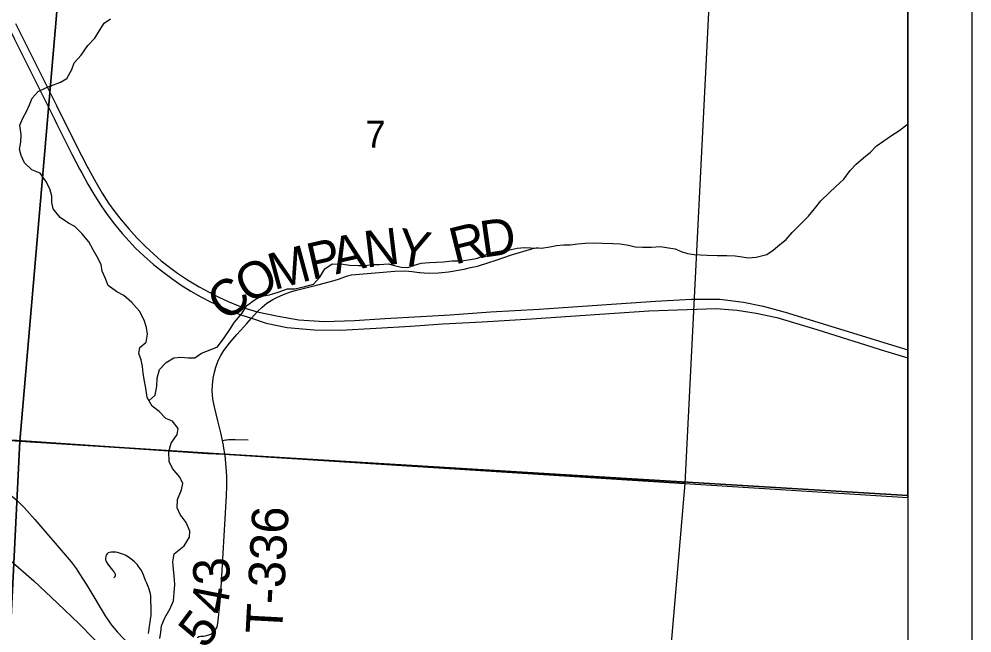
# Model space of a CAD drawing. Extents: x 0 to 34, y 0 to 22.
# Drawn here: x 7.515 to 9, y 18.417 to 19.373 of the extents above; entities that cross this region are included whole.
import ezdxf

# ---------------------------------------------------------------- set-up
doc = ezdxf.new("R2010")
doc.units = 0
for name, color, linetype in [('GM_X_Corporation', 7, 'Continuous'), ('GM_X_County_Road', 7, 'Continuous'), ('GM_X_Minor_River', 7, 'Continuous'), ('GM_X_Rail_Line', 7, 'Continuous'), ('GM_X_Section_Text', 7, 'Continuous'), ('GM_X_Township_Road', 7, 'Continuous'), ('GM_X_Township_Road_Text', 7, 'Continuous'), ('GM_X_Township_Text', 7, 'Continuous'), ('GM_X_US_Route', 7, 'Continuous'), ('SH_Data', 7, 'Continuous')]:
    doc.layers.add(name, color=color, linetype=linetype)

msp = doc.modelspace()

# ---------------------------------------------------------------- linework, layer by layer
at = {"layer": 'GM_X_Corporation'}
for points in [[(8.9, 18.631), (8.9, 20.9), (3.6477, 20.9), (3.6464, 20.8827), (3.5665, 19.797), (3.566, 19.7906), (3.507, 18.9883), (4.2931, 18.935), (4.421, 18.9263), (4.4362, 18.9253), (5.6003, 18.8464), (6.4706, 18.7873), (6.895, 18.7585), (7.0255, 18.7497), (7.0714, 18.7466), (7.0845, 18.7457), (7.389, 18.725), (7.8088, 18.6965), (7.8353, 18.6952)], [(6.5798, 19.8114), (7.5941, 19.7583), (7.5958, 19.6386), (7.5162, 18.7157), (6.5391, 18.7835)], [(7.5941, 19.7583), (8.6057, 19.704), (8.5526, 18.6497), (7.5162, 18.7157), (7.5958, 19.6386)], [(8.9, 18.6277), (8.9, 19.6882), (8.6057, 19.704), (8.5526, 18.6497)], [(7.5162, 18.7157), (7.4643, 17.6703), (6.4386, 17.7441), (6.5391, 18.7835)], [(8.5526, 18.6497), (8.4629, 17.601), (7.4643, 17.6703), (7.5162, 18.7157)]]:
    msp.add_lwpolyline(points, close=True, dxfattribs=at)
at = {"layer": 'GM_X_County_Road'}
msp.add_lwpolyline([(7.3969, 18.717), (7.4409, 18.6782), (7.4478, 18.6722), (7.465, 18.6589), (7.4691, 18.6558), (7.5, 18.633), (7.512, 18.6231), (7.5232, 18.6122), (7.5399, 18.5937), (7.5963, 18.5274), (7.604, 18.5172), (7.6069, 18.5131), (7.6224, 18.4887), (7.6495, 18.4434), (7.6583, 18.4307), (7.6681, 18.4187), (7.6873, 18.3985), (7.6998, 18.3856), (7.7132, 18.3716), (7.7381, 18.3433), (7.7438, 18.3366), (7.7541, 18.3251), (7.7622, 18.3159), (7.7844, 18.2905)], dxfattribs=at)
at = {"layer": 'GM_X_Minor_River'}
for points in [[(7.5451, 19.2602), (7.5579, 19.2667), (7.5685, 19.2706), (7.5798, 19.2745), (7.5896, 19.2803), (7.5971, 19.2944), (7.6011, 19.305), (7.6116, 19.3168), (7.6221, 19.3317), (7.633, 19.3432), (7.6404, 19.355), (7.6475, 19.3668), (7.6577, 19.3734)], [(7.7346, 18.4081), (7.736, 18.418), (7.737, 18.4278), (7.7422, 18.4404), (7.7508, 18.4549), (7.7556, 18.467), (7.757, 18.4796), (7.7577, 18.4921), (7.7568, 18.5053), (7.7556, 18.5163), (7.7547, 18.5277), (7.7569, 18.5402), (7.7726, 18.5528), (7.7809, 18.5658), (7.7812, 18.5753), (7.7757, 18.5889), (7.7662, 18.6013), (7.7615, 18.6115), (7.7618, 18.6247), (7.7681, 18.6396), (7.7703, 18.6498), (7.7657, 18.6596), (7.7542, 18.6728), (7.7488, 18.6837), (7.7487, 18.6993), (7.752, 18.7126), (7.7613, 18.7259), (7.7631, 18.7354), (7.7543, 18.7467), (7.7437, 18.7508), (7.7334, 18.762), (7.7227, 18.7703), (7.7146, 18.7835), (7.7126, 18.7979), (7.7099, 18.8118), (7.7083, 18.8217), (7.7074, 18.8319), (7.7054, 18.8421), (7.7016, 18.8519), (7.7034, 18.8614), (7.7131, 18.8699), (7.7153, 18.8824), (7.7137, 18.8926), (7.7102, 18.9043), (7.7029, 18.9179), (7.6906, 18.9314), (7.6784, 18.9427), (7.6674, 18.9483), (7.6537, 18.958), (7.6491, 18.9701), (7.6448, 18.9803), (7.6428, 18.9905), (7.6367, 19.0029), (7.6305, 19.0135), (7.624, 19.0259), (7.6129, 19.0391), (7.6022, 19.05), (7.5919, 19.0552), (7.579, 19.0642), (7.5683, 19.0777), (7.5659, 19.0875), (7.5659, 19.0974), (7.5631, 19.1084), (7.5569, 19.1208), (7.5478, 19.1332), (7.5348, 19.1384), (7.5238, 19.1493), (7.5184, 19.1606), (7.516, 19.1705), (7.5178, 19.1811), (7.5181, 19.1932), (7.5165, 19.2076), (7.5209, 19.2186), (7.5269, 19.2289), (7.5313, 19.2392), (7.5354, 19.2498), (7.5451, 19.2602)], [(8.8509, 19.1751), (8.8629, 19.1835), (8.8746, 19.1916), (8.8859, 19.1992), (8.899, 19.2088), (8.9, 19.2094)], [(7.7176, 18.7787), (7.7271, 18.787), (7.7296, 18.801), (7.7303, 18.8139), (7.7339, 18.8272), (7.7441, 18.8383), (7.7565, 18.8452), (7.7674, 18.8465), (7.7784, 18.8454), (7.789, 18.8452), (7.7996, 18.8525), (7.8131, 18.8579), (7.8241, 18.8625), (7.8349, 18.8763), (7.8435, 18.8896), (7.851, 18.9007), (7.8626, 18.9152), (7.87, 18.927), (7.8832, 18.9362), (7.893, 18.9416), (7.9055, 18.9436), (7.9187, 18.9479), (7.9334, 18.9526), (7.9447, 18.9531), (7.9606, 18.9566), (7.9738, 18.9602), (7.9836, 18.9712), (7.9914, 18.9842), (8.003, 18.9919), (8.0201, 18.9913), (8.0299, 18.9895), (8.0439, 18.9892), (8.0545, 18.9893), (8.0651, 18.9905), (8.0768, 18.9907), (8.0905, 18.9919), (8.0999, 18.989), (8.1106, 18.9864), (8.1208, 18.9861), (8.1313, 18.9896), (8.1415, 18.9928), (8.1548, 18.994), (8.1657, 18.9945), (8.1763, 18.995), (8.1899, 18.9966), (8.2043, 18.9964), (8.2187, 18.9984), (8.2293, 19.0004), (8.2421, 19.0058), (8.2538, 19.0101), (8.2662, 19.0121), (8.2772, 19.0133), (8.2912, 19.0161), (8.3025, 19.017), (8.3127, 19.0167), (8.3294, 19.0161), (8.3422, 19.0185), (8.3524, 19.0201), (8.3634, 19.0213), (8.374, 19.0214), (8.3857, 19.0227), (8.3974, 19.0239), (8.4107, 19.0244), (8.4243, 19.0238), (8.4406, 19.0235), (8.4519, 19.0229), (8.4648, 19.0211), (8.4754, 19.0185), (8.4864, 19.0175), (8.5004, 19.018), (8.5148, 19.0189), (8.5273, 19.0167), (8.5375, 19.0149), (8.547, 19.0112), (8.5569, 19.0079), (8.5671, 19.0065), (8.5769, 19.0058), (8.5872, 19.0052), (8.603, 19.0049), (8.6178, 19.0047), (8.6311, 19.0044), (8.6417, 19.0026), (8.6511, 19.0012), (8.6636, 19.0021), (8.6806, 19.0064), (8.6904, 19.0129), (8.7005, 19.0221), (8.7103, 19.0298), (8.72, 19.0405), (8.7335, 19.0542), (8.7452, 19.0661), (8.7545, 19.0772), (8.7646, 19.0898), (8.7778, 19.1031), (8.7875, 19.1116), (8.8003, 19.1238), (8.8104, 19.1372), (8.8198, 19.1471), (8.831, 19.1567), (8.8419, 19.1655), (8.8509, 19.1751)]]:
    msp.add_lwpolyline(points, dxfattribs=at)
at = {"layer": 'GM_X_Rail_Line'}
msp.add_lwpolyline([(7.4542, 18.5706), (7.5383, 18.498), (7.5752, 18.4632), (7.6085, 18.4311), (7.6535, 18.3856)], dxfattribs=at)
at = {"layer": 'GM_X_Township_Road'}
for points in [[(8.2568, 18.997), (8.2826, 19.0058), (8.3142, 19.0152)], [(8.3142, 19.0152), (8.3151, 19.0155), (8.3241, 19.0172)], [(8.2186, 18.9859), (8.2295, 18.9883), (8.2473, 18.9938), (8.2568, 18.997)], [(7.87, 18.8991), (7.8772, 18.9072), (7.8862, 18.917), (7.8937, 18.9244), (7.9012, 18.9303), (7.9107, 18.936), (7.9167, 18.9392), (7.9272, 18.9442), (7.9379, 18.948), (7.9493, 18.9515), (7.9643, 18.9549), (7.9805, 18.9589), (8.0061, 18.9656), (8.0144, 18.9684), (8.0251, 18.9725), (8.0331, 18.9744), (8.1009, 18.9803), (8.116, 18.9807), (8.1277, 18.9797), (8.1386, 18.9781), (8.1396, 18.9781)], [(8.1396, 18.9781), (8.1531, 18.9773), (8.1687, 18.9777), (8.1843, 18.9794), (8.2087, 18.9836), (8.2186, 18.9859)], [(7.8338, 18.7077), (7.8336, 18.7087), (7.8323, 18.7165), (7.8293, 18.7286), (7.8249, 18.7473), (7.8197, 18.7688), (7.8171, 18.7808), (7.816, 18.794), (7.8164, 18.8029), (7.8176, 18.8137), (7.8195, 18.8228), (7.8219, 18.831), (7.8244, 18.838), (7.8261, 18.8421), (7.8297, 18.8492), (7.8342, 18.8568), (7.8432, 18.8683), (7.8544, 18.8817), (7.8655, 18.8939), (7.87, 18.8991)], [(7.8323, 18.7165), (7.8371, 18.7175), (7.839, 18.7178), (7.8415, 18.7181), (7.8441, 18.7182), (7.8472, 18.7183), (7.8519, 18.7183), (7.872, 18.7178)], [(7.8295, 18.4786), (7.8385, 18.6303), (7.8391, 18.6462), (7.8388, 18.6612), (7.838, 18.6753), (7.8361, 18.6934), (7.8338, 18.7077)], [(7.7166, 18.4158), (7.7171, 18.419), (7.7182, 18.4275), (7.7192, 18.4336), (7.7201, 18.4389), (7.7207, 18.4432), (7.721, 18.4468), (7.721, 18.45), (7.7207, 18.4587), (7.7205, 18.4653), (7.7205, 18.4707), (7.7203, 18.4745), (7.7197, 18.478), (7.7189, 18.4814), (7.7178, 18.4852), (7.7162, 18.4894), (7.7141, 18.4945), (7.7123, 18.4988), (7.7082, 18.5099), (7.7046, 18.5157), (7.7029, 18.5181), (7.7014, 18.5203), (7.6994, 18.5227), (7.6971, 18.5253), (7.6948, 18.5276), (7.692, 18.5301), (7.69, 18.5318), (7.6879, 18.5335), (7.6856, 18.5351), (7.6832, 18.5365), (7.6806, 18.5379), (7.6778, 18.5391), (7.6749, 18.5402), (7.6715, 18.5412), (7.6684, 18.542), (7.6658, 18.5425), (7.6632, 18.5427), (7.6611, 18.5429), (7.6585, 18.5428), (7.6559, 18.5423), (7.6541, 18.5415), (7.6525, 18.5402), (7.651, 18.5382), (7.6501, 18.5357), (7.6497, 18.533), (7.6498, 18.5317), (7.6499, 18.5306), (7.6502, 18.5296), (7.6507, 18.5283), (7.6513, 18.527), (7.6522, 18.5255), (7.6532, 18.5242), (7.6545, 18.5225), (7.6609, 18.5147), (7.6618, 18.5136), (7.6628, 18.5123), (7.6635, 18.5111), (7.6641, 18.5101), (7.6644, 18.5092), (7.6646, 18.5085), (7.6647, 18.5079), (7.6648, 18.5073), (7.6648, 18.5067), (7.6647, 18.5061), (7.6647, 18.5055), (7.6645, 18.505), (7.6644, 18.5045), (7.6642, 18.5041), (7.6639, 18.5036), (7.6629, 18.5027)], [(7.7937, 18.409), (7.7938, 18.4097), (7.7939, 18.4102), (7.7941, 18.4104), (7.7943, 18.4107), (7.7946, 18.4109), (7.7951, 18.4111), (7.7962, 18.4113), (7.7985, 18.4116), (7.803, 18.4121), (7.805, 18.4123), (7.8074, 18.4128), (7.811, 18.4138), (7.8139, 18.4151), (7.8168, 18.4171), (7.8187, 18.4188), (7.8202, 18.4202), (7.8219, 18.4225), (7.8231, 18.4252), (7.8243, 18.4288), (7.8248, 18.4316), (7.8287, 18.4656), (7.8295, 18.4786)]]:
    msp.add_lwpolyline(points, dxfattribs=at)
at = {"layer": 'GM_X_Township_Text'}
msp.add_lwpolyline([(8.9, 18.631), (7.8353, 18.6952), (7.8088, 18.6965), (7.389, 18.725), (7.0845, 18.7457), (7.0714, 18.7466), (7.0255, 18.7497), (6.895, 18.7585), (6.4706, 18.7873), (5.6003, 18.8464), (4.4362, 18.9253), (4.421, 18.9263), (4.2931, 18.935), (3.507, 18.9883), (3.3951, 17.2616), (3.3516, 16.5898), (3.3059, 15.8844), (3.2844, 15.554), (3.2339, 14.7735), (3.1919, 14.1255), (3.1902, 14.1)], dxfattribs=at)
at = {"layer": 'GM_X_US_Route'}
msp.add_line((7.5697, 19.2182), (7.5741, 19.2093), dxfattribs=at)
for points in [[(6.8829, 19.9632), (6.8898, 19.9587), (6.8988, 19.9528), (7.0179, 19.8705), (7.14, 19.7863), (7.2051, 19.7425), (7.2479, 19.7113), (7.291, 19.6741), (7.3163, 19.6501), (7.3384, 19.6267), (7.3637, 19.5971), (7.396, 19.5553), (7.4242, 19.507), (7.4347, 19.4882), (7.4469, 19.4651), (7.4768, 19.405), (7.5077, 19.3427), (7.5357, 19.2865), (7.563, 19.2314), (7.5697, 19.2182)], [(7.5097, 19.3661), (7.5736, 19.2384), (7.6027, 19.1799), (7.6225, 19.1412), (7.6239, 19.1385)], [(7.5741, 19.2093), (7.5975, 19.1625), (7.6099, 19.1386)], [(7.6099, 19.1386), (7.6127, 19.1333), (7.6223, 19.1159), (7.6331, 19.0978), (7.6431, 19.0821), (7.6526, 19.0684), (7.6638, 19.0535), (7.6756, 19.0392), (7.6864, 19.0271), (7.6967, 19.0164), (7.7097, 19.004), (7.7246, 18.9909), (7.7386, 18.9796), (7.753, 18.9689), (7.7678, 18.9587), (7.783, 18.9491), (7.7981, 18.9405), (7.8123, 18.933), (7.828, 18.9256), (7.8446, 18.9186), (7.8608, 18.9126), (7.8772, 18.9072), (7.9002, 18.8994), (7.9328, 18.8924), (7.975, 18.8888), (8.0162, 18.8884), (8.0716, 18.8918), (8.1251, 18.8947), (8.1757, 18.8982), (8.2365, 18.9016), (8.3135, 18.9063), (8.3973, 18.9116), (8.4966, 18.9184), (8.5563, 18.9208), (8.6009, 18.922), (8.634, 18.9195), (8.664, 18.915), (8.6958, 18.908), (8.7581, 18.8894), (8.8636, 18.8561), (8.9, 18.8453)], [(7.6239, 19.1385), (7.6346, 19.1188), (7.6447, 19.1016), (7.6546, 19.0865), (7.6645, 19.0729), (7.6744, 19.0601), (7.686, 19.0463), (7.6986, 19.0325), (7.7117, 19.0192), (7.7254, 19.0064), (7.7367, 18.9967), (7.7494, 18.9866), (7.7619, 18.9774), (7.7775, 18.967), (7.7955, 18.9561), (7.8113, 18.9474), (7.8275, 18.9393), (7.8411, 18.9331), (7.8561, 18.9271), (7.8707, 18.9219), (7.8862, 18.917), (7.9189, 18.9103), (7.9509, 18.9046), (7.9904, 18.902), (8.0377, 18.9037), (8.0853, 18.9067), (8.1409, 18.9097), (8.187, 18.9122), (8.2499, 18.9169), (8.3254, 18.9212), (8.4083, 18.9267), (8.5071, 18.9338), (8.5632, 18.9368), (8.6071, 18.9368), (8.6438, 18.9323), (8.6749, 18.9259), (8.709, 18.9165), (8.7668, 18.8988), (8.8762, 18.8651), (8.9, 18.8579)]]:
    msp.add_lwpolyline(points, dxfattribs=at)
at = {"layer": 'SH_Data'}
for p, q in [((9, 21), (9, 14)), ((8.9, 20.9), (8.9, 14.1))]:
    msp.add_line(p, q, dxfattribs=at)

# ---------------------------------------------------------------- texts
at = {"layer": 'GM_X_Section_Text'}
msp.add_text('7', height=0.0419, rotation=0, dxfattribs=at).set_placement((8.055, 19.1727))
at = {"layer": 'GM_X_Township_Road_Text'}
for s, height, rotation, p in [('R', 0.0568, 13.9548, (8.1941, 18.9904)), ('D', 0.0568, 8.11, (8.2379, 19.0014)), ('A', 0.0568, 12.7074, (8.0086, 18.9751)), ('N', 0.0568, 6.8431, (8.0558, 18.9858)), ('Y', 0.0568, 350.8694, (8.1013, 18.9919)), ('P', 0.0568, 12.7963, (7.9712, 18.9666)), ('M', 0.0568, 15.1453, (7.9123, 18.9507)), ('O', 0.0568, 28.0706, (7.8713, 18.9284)), ('C', 0.0568, 41.006, (7.8389, 18.8997)), ('T-336', 0.05682, 86.913, (7.9248, 18.4143)), ('3', 0.0568, 94.116, (7.8446, 18.4941)), ('4', 0.0568, 78.9309, (7.8369, 18.4434)), ('5', 0.0568, 53.1908, (7.8048, 18.3902))]:
    msp.add_text(s, height=height, rotation=rotation, dxfattribs=at).set_placement(p)

doc.saveas('drawing.dxf')
